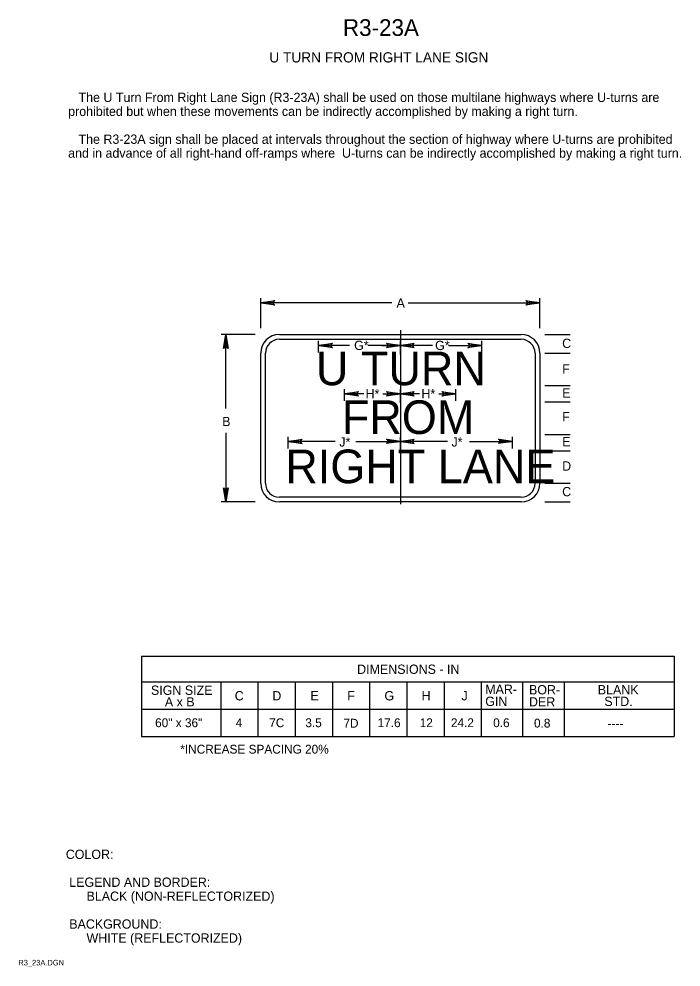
# Model space of a CAD drawing. Extents: x 0.5 to 7.5, y 0.2 to 10.2.
import ezdxf

# ---------------------------------------------------------------- set-up
doc = ezdxf.new("R2010")
doc.units = 0
for name, color, linetype in [('1', 7, 'Continuous'), ('11', 7, 'Continuous'), ('12', 7, 'Continuous'), ('2', 7, 'Continuous'), ('3', 7, 'Continuous')]:
    doc.layers.add(name, color=color, linetype=linetype)

# ---------------------------------------------------------------- blocks, each defined once
blk = doc.blocks.new('RARROW')
at = {"layer": '3'}
for p, q in [((-84.9, 11.2), (-89.2, 15.1)), ((-89.2, 15.1), (0, 0)), ((0, 0), (-89.2, -14.9)), ((-84.9, 11.2), (-81.7, 4.8)), ((0, 0), (-84.9, 11.2)), ((-84.6, -10.6), (0, 0)), ((-81.7, 4.8), (0, 0)), ((0, 0), (-81.7, -4.3)), ((-89.2, -14.9), (-84.6, -10.6)), ((-81.7, -4.3), (-84.6, -10.6))]:
    blk.add_line(p, q, dxfattribs=at)

msp = doc.modelspace()

# ---------------------------------------------------------------- linework, layer by layer
at = {"layer": '11'}
for p, q in [((3.253, 6.85), (5.812, 6.85)), ((3.056, 5.275), (3.056, 6.653)), ((6.009, 6.653), (6.009, 5.275)), ((5.812, 5.078), (3.253, 5.078))]:
    msp.add_line(p, q, dxfattribs=at)
for centre, start, end in [((3.253, 6.653), 90, 180), ((5.812, 6.653), 0, 90), ((3.253, 5.275), 180, 270), ((5.812, 5.275), 270, 0)]:
    msp.add_arc(centre, 0.197, start, end, dxfattribs=at)
at = {"layer": '3'}
for p, q in [((3.056, 6.917), (3.056, 7.234)), ((6.009, 6.917), (6.009, 7.234)), ((4.444, 7.185), (3.056, 7.185)), ((4.616, 7.185), (6.009, 7.185)), ((2.997, 6.85), (2.638, 6.85)), ((2.687, 6.068), (2.687, 6.85)), ((4.533, 6.896), (4.533, 5.054)), ((6.063, 6.85), (6.329, 6.85)), ((3.253, 6.799), (5.812, 6.799)), ((3.669, 6.659), (3.669, 6.782)), ((3.995, 6.733), (3.669, 6.733)), ((4.533, 6.733), (4.194, 6.733)), ((4.336, 6.733), (4.533, 6.733)), ((4.392, 6.752), (4.385, 6.758)), ((4.385, 6.758), (4.533, 6.733)), ((4.533, 6.733), (4.385, 6.709)), ((4.392, 6.752), (4.398, 6.741)), ((4.533, 6.733), (4.392, 6.752)), ((4.393, 6.716), (4.533, 6.733)), ((4.398, 6.726), (4.393, 6.716)), ((4.398, 6.741), (4.533, 6.733)), ((4.533, 6.733), (4.398, 6.726)), ((4.533, 6.64), (4.533, 6.782)), ((4.872, 6.733), (4.533, 6.733)), ((5.045, 6.733), (5.396, 6.733)), ((5.396, 6.659), (5.396, 6.782)), ((3.108, 5.275), (3.108, 6.653)), ((4.385, 6.709), (4.393, 6.716)), ((5.958, 6.653), (5.958, 5.275)), ((6.063, 6.653), (6.329, 6.653)), ((3.944, 6.147), (3.944, 6.27)), ((4.533, 6.127), (4.533, 6.27)), ((5.121, 6.147), (5.121, 6.27)), ((6.063, 6.309), (6.329, 6.309)), ((4.148, 6.221), (3.944, 6.221)), ((4.347, 6.221), (4.551, 6.221)), ((4.735, 6.221), (4.533, 6.221)), ((4.941, 6.221), (5.121, 6.221)), ((6.063, 6.136), (6.329, 6.136)), ((2.687, 5.809), (2.687, 5.078)), ((3.346, 5.645), (3.346, 5.768)), ((4.533, 5.625), (4.533, 5.768)), ((5.72, 5.645), (5.72, 5.768)), ((6.063, 5.792), (6.329, 5.792)), ((3.845, 5.719), (3.346, 5.719)), ((4.063, 5.719), (4.533, 5.719)), ((5.032, 5.719), (4.533, 5.719)), ((5.265, 5.719), (5.72, 5.719)), ((6.063, 5.62), (6.329, 5.62)), ((6.063, 5.275), (6.329, 5.275)), ((5.812, 5.129), (3.253, 5.129)), ((2.997, 5.078), (2.638, 5.078)), ((6.063, 5.078), (6.329, 5.078)), ((6.063, 5.078), (6.329, 5.078)), ((1.796, 3.445), (7.429, 3.445)), ((1.796, 3.445), (1.796, 2.594)), ((7.429, 3.445), (7.429, 2.594)), ((1.796, 3.174), (7.429, 3.174)), ((2.635, 3.174), (2.635, 2.594)), ((3.027, 3.174), (3.027, 2.594)), ((3.42, 3.174), (3.42, 2.594)), ((3.814, 3.174), (3.814, 2.594)), ((4.208, 3.174), (4.208, 2.594)), ((4.601, 3.174), (4.601, 2.594)), ((4.995, 3.174), (4.995, 2.594)), ((5.389, 3.174), (5.389, 2.594)), ((5.389, 3.174), (5.389, 2.594)), ((5.827, 3.174), (5.827, 2.594)), ((6.265, 3.174), (6.265, 2.594)), ((1.796, 2.884), (7.429, 2.884)), ((1.796, 2.594), (7.429, 2.594))]:
    msp.add_line(p, q, dxfattribs=at)
for centre, start, end in [((3.253, 6.653), 90, 180), ((5.812, 6.653), 0, 90), ((3.253, 5.275), 180, 270), ((5.812, 5.275), 270, 0)]:
    msp.add_arc(centre, 0.146, start, end, dxfattribs=at)

# ---------------------------------------------------------------- block references
at = {"layer": '3', "xscale": 0.0016545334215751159, "yscale": 0.0016366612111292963}
for p, rotation in [((3.056, 7.185), 180), ((2.687, 6.85), 90), ((3.669, 6.733), 180), ((4.533, 6.733), 180), ((3.944, 6.221), 180), ((4.533, 6.221), 180), ((3.346, 5.719), 180), ((4.533, 5.719), 180), ((2.687, 5.078), -90)]:
    msp.add_blockref('RARROW', p, dxfattribs=dict(at, rotation=rotation))
for p in [(6.009, 7.185), (4.533, 6.733), (5.396, 6.733), (4.533, 6.221), (5.121, 6.221), (4.533, 5.719), (4.533, 5.719), (5.72, 5.719)]:
    msp.add_blockref('RARROW', p, dxfattribs=at)

# ---------------------------------------------------------------- texts
at = {"layer": '1'}
for s, height, p in [('R3-23A', 0.1772, (3.926, 10.01)), ('U TURN FROM RIGHT LANE SIGN', 0.10828, (3.147, 9.729)), ('COLOR:', 0.0984, (0.994, 1.299)), (' LEGEND AND BORDER:', 0.09842, (0.994, 1.004)), ('      BLACK (NON-REFLECTORIZED)', 0.09842, (0.994, 0.856)), (' BACKGROUND:', 0.09842, (0.994, 0.561)), ('      WHITE (REFLECTORIZED)', 0.09842, (0.994, 0.413)), ('R3_23A.DGN', 0.0591, (0.492, 0.172))]:
    msp.add_text(s, height=height, dxfattribs=at).set_placement(p)
at = {"layer": '12'}
for s, p in [('U TURN', (3.64, 6.313)), ('FROM', (3.914, 5.797)), ('RIGHT LANE', (3.316, 5.276))]:
    msp.add_text(s, height=0.356, dxfattribs=at).set_placement(p)
at = {"layer": '2'}
for s, height, p in [('   The U Turn From Right Lane Sign (R3-23A) shall be used on those multilane highways where U-turns are ', 0.098415, (1.019, 9.311)), ('prohibited but when these movements can be indirectly accomplished by making a right turn.', 0.09842, (1.019, 9.163)), ('   The R3-23A sign shall be placed at intervals throughout the section of highway where U-turns are prohibited ', 0.098415, (1.019, 8.868)), ('and in advance of all right-hand off-ramps where  U-turns can be indirectly accomplished by making a right turn.', 0.098415, (1.019, 8.721))]:
    msp.add_text(s, height=height, dxfattribs=at).set_placement(p)
at = {"layer": '3'}
for s, height, p in [('A', 0.0984, (4.493, 7.135)), ('G*', 0.0984, (4.044, 6.686)), ('G*', 0.0984, (4.901, 6.685)), ('C', 0.0984, (6.245, 6.707)), ('F', 0.0984, (6.245, 6.437)), ('H*', 0.0984, (4.165, 6.173)), ('H*', 0.0984, (4.756, 6.173)), ('E', 0.0984, (6.245, 6.181)), ('F', 0.0984, (6.245, 5.931)), ('B', 0.0984, (2.648, 5.88)), ('J*', 0.0984, (3.887, 5.664)), ('J*', 0.0984, (5.074, 5.664)), ('E', 0.0984, (6.245, 5.666)), ('D', 0.0984, (6.245, 5.409)), ('C', 0.0984, (6.245, 5.138)), ('DIMENSIONS - IN', 0.09842, (4.076, 3.258)), ('SIGN SIZE', 0.0984, (1.895, 3.036)), ('MAR-', 0.0984, (5.431, 3.046)), ('BOR-', 0.0984, (5.894, 3.041)), ('BLANK', 0.0984, (6.622, 3.041)), ('A x B', 0.0984, (2.042, 2.913)), ('C', 0.0984, (2.781, 2.977)), ('D', 0.0984, (3.179, 2.977)), ('E', 0.0984, (3.582, 2.977)), ('F', 0.0984, (3.972, 2.977)), ('G', 0.0984, (4.365, 2.977)), ('H', 0.0984, (4.758, 2.977)), ('J', 0.0984, (5.18, 2.977)), ('GIN', 0.0984, (5.431, 2.918)), ('DER', 0.0984, (5.894, 2.913)), ('STD.', 0.0984, (6.691, 2.918)), ('60" x 36"', 0.0935, (1.939, 2.694)), ('4', 0.0935, (2.791, 2.694)), ('7C', 0.0935, (3.146, 2.694)), ('3.5', 0.0935, (3.528, 2.694)), ('7D', 0.0935, (3.931, 2.689)), ('17.6', 0.0935, (4.292, 2.694)), ('12', 0.0935, (4.738, 2.694)), ('24.2', 0.0935, (5.068, 2.694)), ('0.6', 0.0935, (5.515, 2.694)), ('0.8', 0.0935, (5.947, 2.69)), ('----', 0.0935, (6.726, 2.687)), ('*INCREASE SPACING 20%', 0.09351, (2.205, 2.414))]:
    msp.add_text(s, height=height, dxfattribs=at).set_placement(p)

doc.saveas('drawing.dxf')
